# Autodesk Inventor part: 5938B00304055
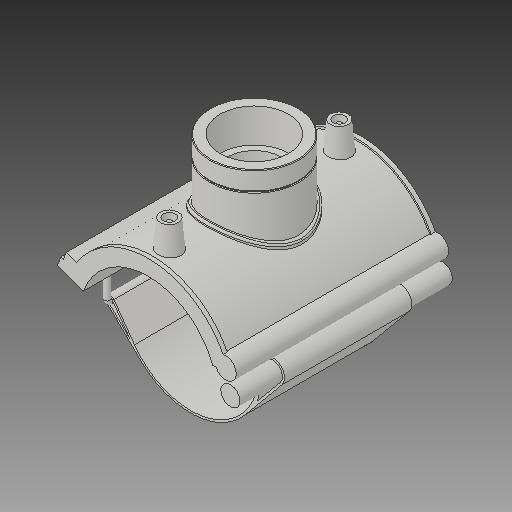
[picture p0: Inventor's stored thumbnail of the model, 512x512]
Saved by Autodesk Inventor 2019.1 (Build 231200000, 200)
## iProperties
Created: 2017-07
Part Number: 5938B00304055
Material: Generic
Description: PLASSON TRANSITION SADDLE 4''IPS x 2"NPT
Document SubType Name: Modeling
Designer: KIM
Density: 1 g/cm^3
Appearance: Default
Author: KIM
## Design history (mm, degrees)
derived "5938B.ipt"
feature "Solid1::5938B.ipt"
tag "TaggingFeature1"
body "Solid1"
other parameters: "d_" = 114.1, "B_" = 156.21, "H_" = 46.736, "L_" = 176.022, "d_t" = 6, "G_" = 56.656, "d148" = 1.7115, "d160" = 1.7115, "d169" = 1.7115, "d192" = 4.564, "d0" = 114.1, "d1" = 136.92, "d2" = 390.525, "d3" = 28.525, "d4" = 176.022, "d5" = 0, "d40" = 71.1984, "d41" = 79.3184, "d43" = 0, "d45" = 0, "d47" = 115.196, "d48" = 73.6528, "d50" = 0, "d78" = 90.46, "d79" = 15, "d80" = 70.4088, "d82" = 5 deg, "d84" = 4, "d85" = 14, "d86" = 0, "d87" = 3, "d88" = 0, "d96" = 139.6584, "d97" = 3.52044, "d98" = 0, "d102" = 1.69968, "d103" = 56.656, "d104" = 28.0416, "d105" = 0, "d106" = 45.3248, "d108" = 0, "d109" = -15.57867, "d111" = 0.5, "d112" = 0.5, "d113" = 0, "d114" = 0.5, "d117" = 0.56656, "d120" = 140 deg, "d121" = 24.228, "d122" = 20 deg, "d123" = 547.68, "d124" = 82.152, "d126" = 0, "d143" = 117.523, "d145" = 17.55385, "d149" = 1.7115, "d150" = 19.30923, "d153" = 176.022, "d154" = 0, "d156" = 68.46, "d157" = 160 deg, "d159" = 4.564, "d161" = 1.7115, "d162" = 105.6132, "d163" = 0, "d164" = 57.05, "d167" = 11.41, "d168" = 66.79024, "d170" = 1.7115, "d172" = 0, "d173" = 1, "d175" = 57.05, "d176" = 20 deg, "d177" = 7.987, "d178" = 22.82, "d180" = 0, "d183" = 9.128, "d184" = 6.3896, "d185" = 57.20715, "d186" = 57.20715, "d187" = 68.46, "d188" = 6.846, "d189" = 7.987, "d190" = 0, "d191" = 82.152, "d193" = 4.564, "d194" = 2.33905, "d195" = 90 deg, "d197" = 0, "d199" = 0
